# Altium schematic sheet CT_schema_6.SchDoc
size 274 x 160 mm
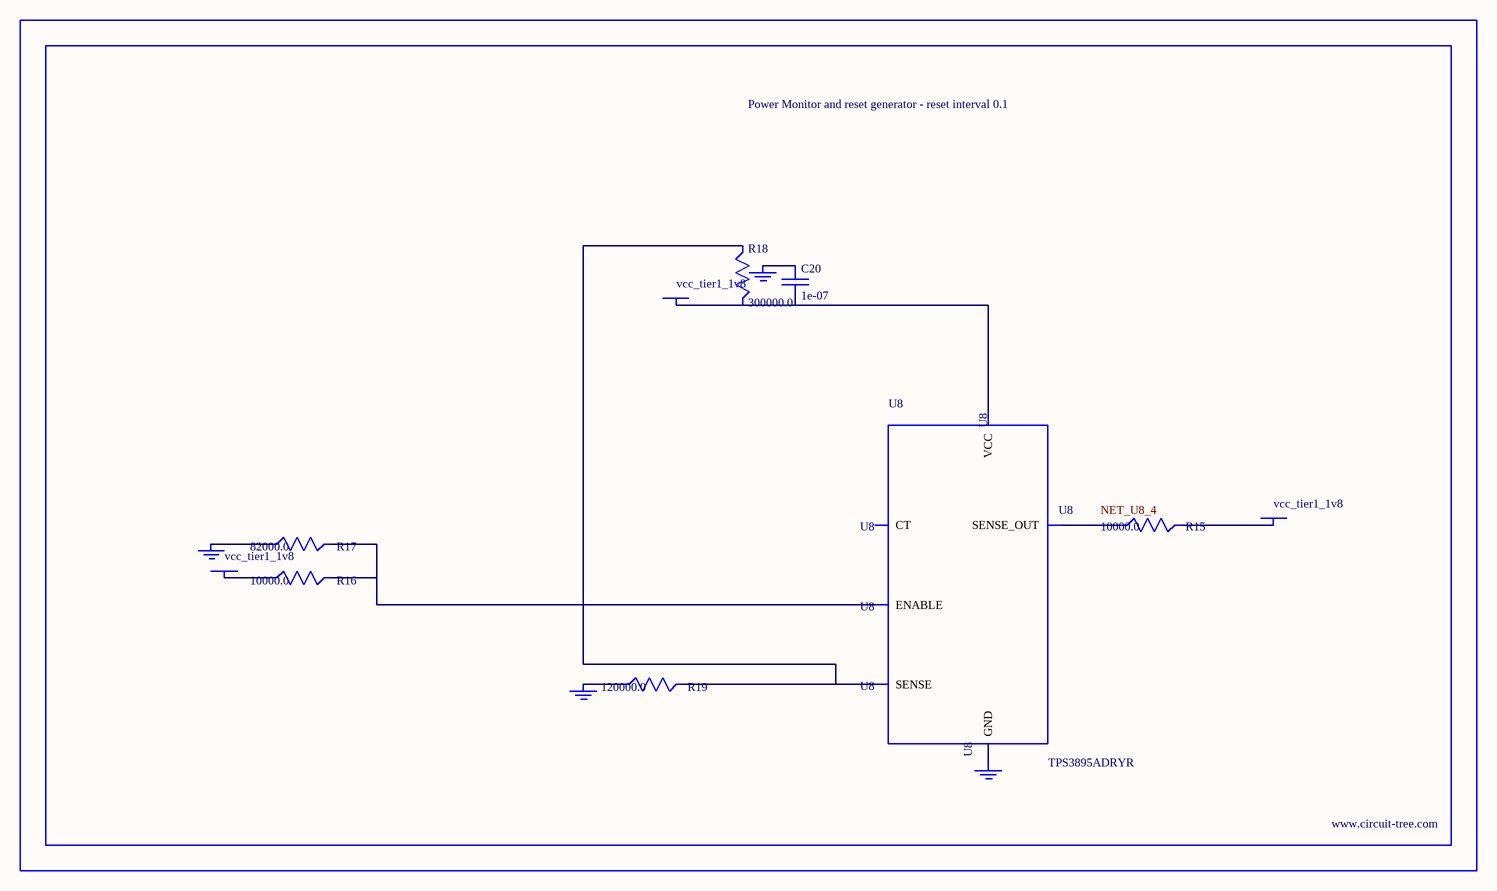
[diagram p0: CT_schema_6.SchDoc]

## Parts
BORDER5  (no value)
C20  1e-07  [C0402]
GND_INSTANCE_5_0  (no value)
GND_INSTANCE_5_1  (no value)
GND_INSTANCE_5_2  (no value)
GND_INSTANCE_5_3  (no value)
POWER_INSTANCE_5_0  vcc_tier1_1v8
POWER_INSTANCE_5_1  vcc_tier1_1v8
POWER_INSTANCE_5_2  vcc_tier1_1v8
R15  10000.0  [R0603]
R16  10000.0  [R0603]
R17  82000.0  [R0603]
R18  300000.0  [R0603]
R19  120000.0  [R0603]
U8  TPS3895ADRYR  [SON-6]

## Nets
NetC20_1: C20.1 GND_INSTANCE_5_2.0(GND)
NetC20_2: C20.2 POWER_INSTANCE_5_2.0(PWR) R18.2 U8.6(VCC)
NetGND_INSTANCE_5_0_0: GND_INSTANCE_5_0.0(GND) R17.1
NetGND_INSTANCE_5_1_0: GND_INSTANCE_5_1.0(GND) R19.1
NetGND_INSTANCE_5_3_0: GND_INSTANCE_5_3.0(GND) U8.2(GND)
NetPOWER_INSTANCE_5_0_0: POWER_INSTANCE_5_0.0(PWR) R16.1
NetPOWER_INSTANCE_5_1_0: POWER_INSTANCE_5_1.0(PWR) R15.2
NetR15_1: R15.1 U8.4(SENSE_OUT)
NetR16_2: R16.2 R17.2 U8.1(ENABLE)
NetR18_1: R18.1 R19.2 U8.3(SENSE)

Not connected (* = marked no-connect by the designer): U8 5(CT)

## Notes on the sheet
- Labels drawn without touching a wire or pin: NET_U8_4

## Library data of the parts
BORDER5 = BORDER_PAGE5
C20 = C0402C104K3RACTU
GND_INSTANCE_5_0-GND_INSTANCE_5_3 = GND
POWER_INSTANCE_5_0-POWER_INSTANCE_5_2 = PWR
R15 R16 = RC0603JR-0710KL
R17 = RC0603JR-0782KL
R18 = RC0603JR-07300KL
R19 = RC0603JR-07120KL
